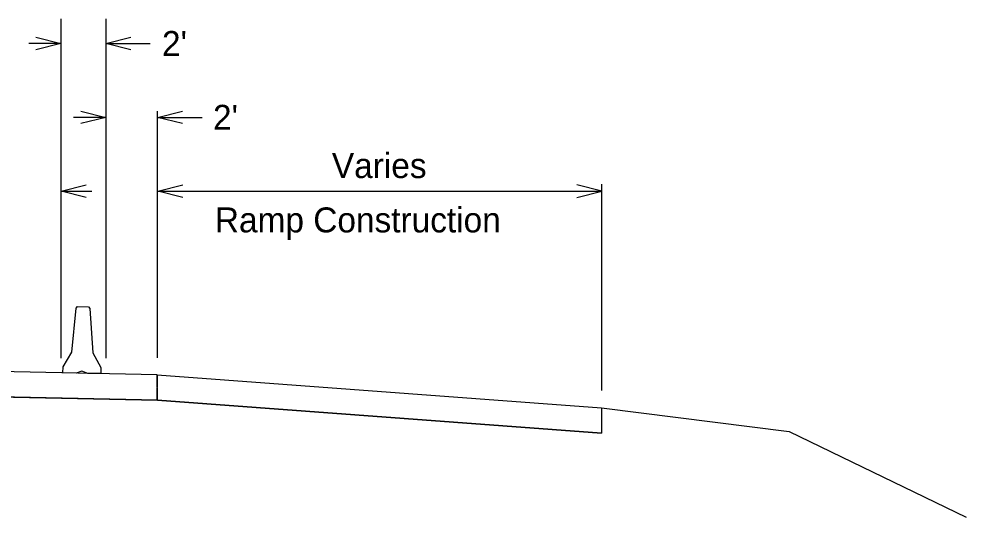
# Model space of a CAD drawing. Extents: x 10133 to 81668, y 4856 to 11018.
# Drawn here: x 13786 to 14408, y 6172 to 6498 of the extents above; entities that cross this region are included whole.
import ezdxf

# ---------------------------------------------------------------- set-up
doc = ezdxf.new("R2010")
doc.units = 0
for name, color, linetype in [('dsnXsPCCPavement', 7, 'Continuous'), ('dsnXsPCCPavementBottom', 7, 'Continuous'), ('dsnXsShldrEarthFill', 7, 'Continuous'), ('dsnXsShldrGranular', 7, 'Continuous'), ('dsnXsShldrGranularBottom', 7, 'Continuous'), ('dsnXsShldrSpecialBackBottom', 7, 'Continuous')]:
    doc.layers.add(name, color=color, linetype=linetype)

msp = doc.modelspace()

# ---------------------------------------------------------------- linework, layer by layer
at = {"layer": 'dsnXsPCCPavement'}
msp.add_lwpolyline([(13815.14, 6270.16), (13820.82, 6279.62), (13823.72, 6308.6), (13824.65, 6309.61), (13831.82, 6309.48), (13832.72, 6308.45), (13834.62, 6279.38), (13839.97, 6269.73), (13839.9, 6265.63), (13831.35, 6265.78), (13827.51, 6267.21), (13823.62, 6265.91), (13815.07, 6266.06)], close=True, dxfattribs=at)
at = {"layer": 'dsnXsPCCPavementBottom'}
for p, q in [((13813.72, 6498.41), (13813.72, 6275.72)), ((13843.09, 6498.41), (13843.09, 6275.72)), ((13813.72, 6482.29), (13792.58, 6482.29)), ((13843.09, 6482.29), (13872.34, 6482.29)), ((13843.09, 6433.83), (13821.95, 6433.83)), ((13877.13, 6276.07), (13877.13, 6437.93)), ((13877.13, 6433.83), (13906.38, 6433.83)), ((14168.59, 6254.48), (14168.59, 6389.87)), ((13813.8, 6385.38), (13834.03, 6385.38)), ((13877.2, 6385.38), (14168.59, 6385.38))]:
    msp.add_line(p, q, dxfattribs=at)
for points in [[(13797.33, 6486.39), (13813.72, 6482.29), (13797.33, 6478.19)], [(13859.48, 6478.19), (13843.09, 6482.29), (13859.48, 6486.39)], [(13826.7, 6437.93), (13843.09, 6433.83), (13826.7, 6429.73)], [(13893.52, 6429.73), (13877.13, 6433.83), (13893.52, 6437.93)], [(13830.19, 6381.28), (13813.8, 6385.38), (13830.19, 6389.47)], [(13893.6, 6381.28), (13877.2, 6385.38), (13893.6, 6389.47)], [(14152.2, 6381.28), (14168.59, 6385.38), (14152.2, 6389.47)]]:
    msp.add_lwpolyline(points, dxfattribs=at)
at = {"layer": 'dsnXsShldrGranular'}
msp.add_line((13678.11, 6252.46), (13877.13, 6248.23), dxfattribs=at)
msp.add_lwpolyline([(13877.13, 6248.23), (13876.89, 6264.79), (13678.46, 6269.01)], dxfattribs=at)
msp.add_lwpolyline([(13876.89, 6264.79), (14168.51, 6243.09), (14168.51, 6226.49), (13877.13, 6248.17)], close=True, dxfattribs=at)
at = {"layer": 'dsnXsShldrGranularBottom'}
for p, q in [((13876.89, 6264.79), (13876.72, 6248.23)), ((14168.51, 6243.09), (14291.62, 6227.62)), ((14291.62, 6227.62), (14407.61, 6171.51))]:
    msp.add_line(p, q, dxfattribs=at)
at = {"layer": 'dsnXsShldrSpecialBackBottom'}
for p, q in [((13876.89, 6264.79), (14168.51, 6243.09)), ((13877.13, 6248.17), (14168.51, 6226.49)), ((14168.51, 6243.09), (14168.51, 6226.49))]:
    msp.add_line(p, q, dxfattribs=at)
for points in [[(13876.89, 6264.79), (13678.46, 6269.01), (13480.02, 6264.79), (13382.38, 6257.53)], [(13877.13, 6248.23), (13678.81, 6252.46), (13479.78, 6248.17), (13382.38, 6240.92)]]:
    msp.add_lwpolyline(points, dxfattribs=at)

# ---------------------------------------------------------------- texts
at = {"layer": 'dsnXsShldrEarthFill'}
for s, height, p in [("2'", 16.391, (13880.04, 6474.09)), ("2'", 16.391, (13913.51, 6425.64)), ('Varies', 16.391, (13991.5, 6393.97)), ('Ramp Construction', 16.3906, (13914.73, 6358.32))]:
    msp.add_text(s, height=height, dxfattribs=at).set_placement(p)

doc.saveas('drawing.dxf')
